// Mitsubishi GX Works2 project: Leser01-MF   PLC: Q03UDE
// Leser01-MF

PROGRAM MAIN
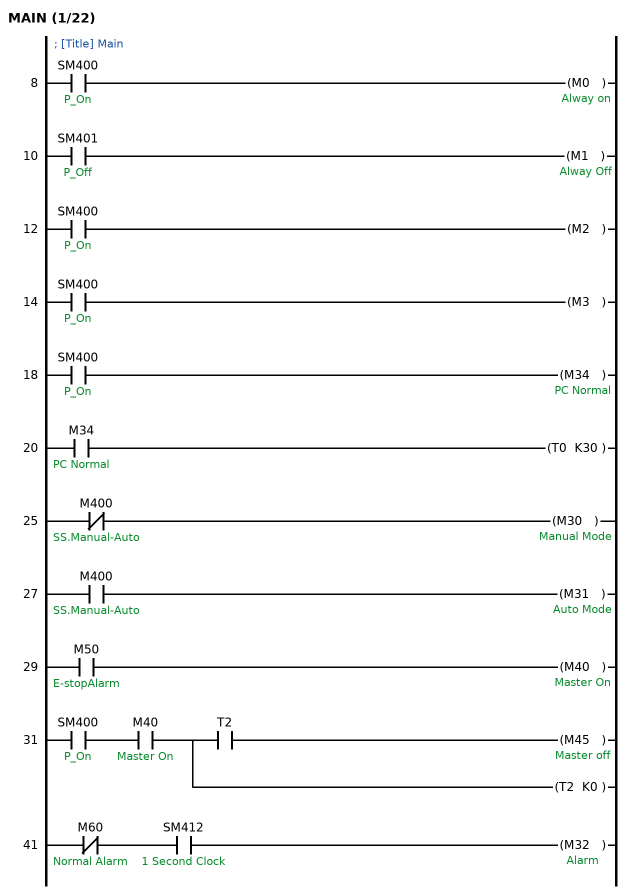
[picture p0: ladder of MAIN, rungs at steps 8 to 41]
; [Title] Main
8     LD      SM400  ; P_On
      OUT     M0  ; Alway on
10    LD      SM401  ; P_Off
      OUT     M1  ; Alway Off
12    LD      SM400  ; P_On
      OUT     M2
14    LD      SM400  ; P_On
      OUT     M3
; 
18    LD      SM400  ; P_On
      OUT     M34  ; PC Normal
20    LD      M34  ; PC Normal
      OUT     T0 K30
25    LDI     M400  ; SS.Manual-Auto
      OUT     M30  ; Manual Mode
27    LD      M400  ; SS.Manual-Auto
      OUT     M31  ; Auto Mode
29    LD      M50  ; E-stopAlarm
      OUT     M40  ; Master On
31    LD      SM400  ; P_On
      AND     M40  ; Master On
      MPS
      AND     T2
      OUT     M45  ; Master off
      MPP
      OUT     T2 K0
41    LDI     M60  ; Normal Alarm
      AND     SM412  ; 1 Second Clock
      OUT     M32  ; Alarm
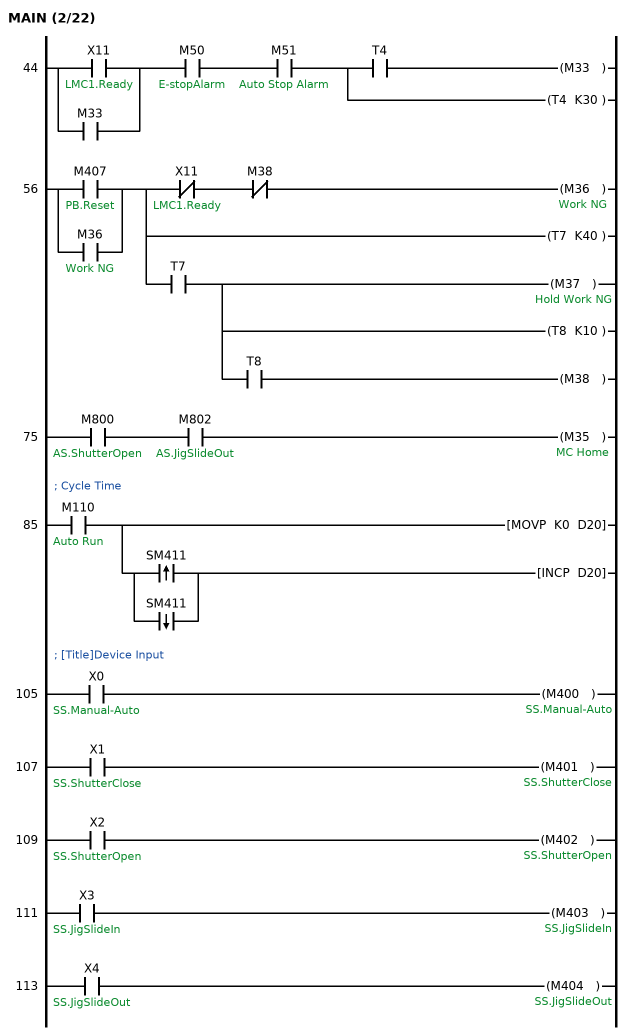
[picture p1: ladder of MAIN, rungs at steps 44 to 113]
44    LD      X11  ; LMC1.Ready
      OR      M33
      AND     M50  ; E-stopAlarm
      AND     M51  ; Auto Stop Alarm
      MPS
      AND     T4
      OUT     M33
      MPP
      OUT     T4 K30
56    LD      M407  ; PB.Reset
      OR      M36  ; Work NG
      MPS
      ANI     X11  ; LMC1.Ready
      ANI     M38
      OUT     M36  ; Work NG
      MPP
      OUT     T7 K40
      AND     T7
      OUT     M37  ; Hold Work NG
      OUT     T8 K10
      AND     T8
      OUT     M38
75    LD      M800  ; AS.ShutterOpen
      AND     M802  ; AS.JigSlideOut
      OUT     M35  ; MC Home
; Cycle Time
85    LD      M110  ; Auto Run
      MOVP    K0 D20
      LDP     SM411
      ORF     SM411
      ANB
      INCP    D20
; [Title]Device Input
105   LD      X0  ; SS.Manual-Auto
      OUT     M400  ; SS.Manual-Auto
107   LD      X1  ; SS.ShutterClose
      OUT     M401  ; SS.ShutterClose
109   LD      X2  ; SS.ShutterOpen
      OUT     M402  ; SS.ShutterOpen
111   LD      X3  ; SS.JigSlideIn
      OUT     M403  ; SS.JigSlideIn
113   LD      X4  ; SS.JigSlideOut
      OUT     M404  ; SS.JigSlideOut
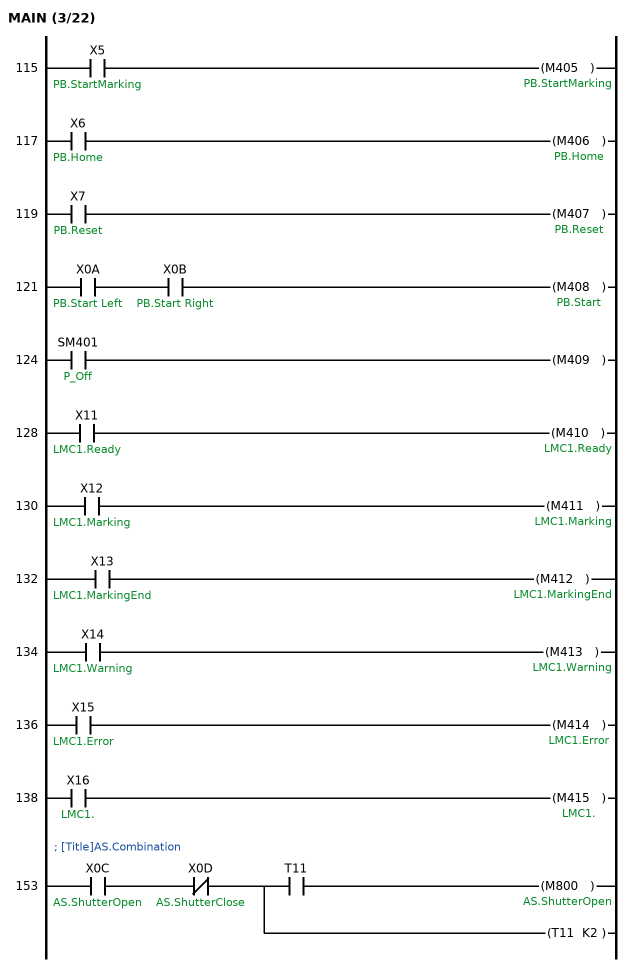
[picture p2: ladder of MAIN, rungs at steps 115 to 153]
115   LD      X5  ; PB.StartMarking
      OUT     M405  ; PB.StartMarking
117   LD      X6  ; PB.Home
      OUT     M406  ; PB.Home
119   LD      X7  ; PB.Reset
      OUT     M407  ; PB.Reset
121   LD      X0A  ; PB.Start Left
      AND     X0B  ; PB.Start Right
      OUT     M408  ; PB.Start
124   LD      SM401  ; P_Off
      OUT     M409
; 
128   LD      X11  ; LMC1.Ready
      OUT     M410  ; LMC1.Ready
130   LD      X12  ; LMC1.Marking
      OUT     M411  ; LMC1.Marking
132   LD      X13  ; LMC1.MarkingEnd
      OUT     M412  ; LMC1.MarkingEnd
134   LD      X14  ; LMC1.Warning
      OUT     M413  ; LMC1.Warning
136   LD      X15  ; LMC1.Error
      OUT     M414  ; LMC1.Error
138   LD      X16  ; LMC1.
      OUT     M415  ; LMC1.
; [Title]AS.Combination
153   LD      X0C  ; AS.ShutterOpen
      ANI     X0D  ; AS.ShutterClose
      MPS
      AND     T11
      OUT     M800  ; AS.ShutterOpen
      MPP
      OUT     T11 K2
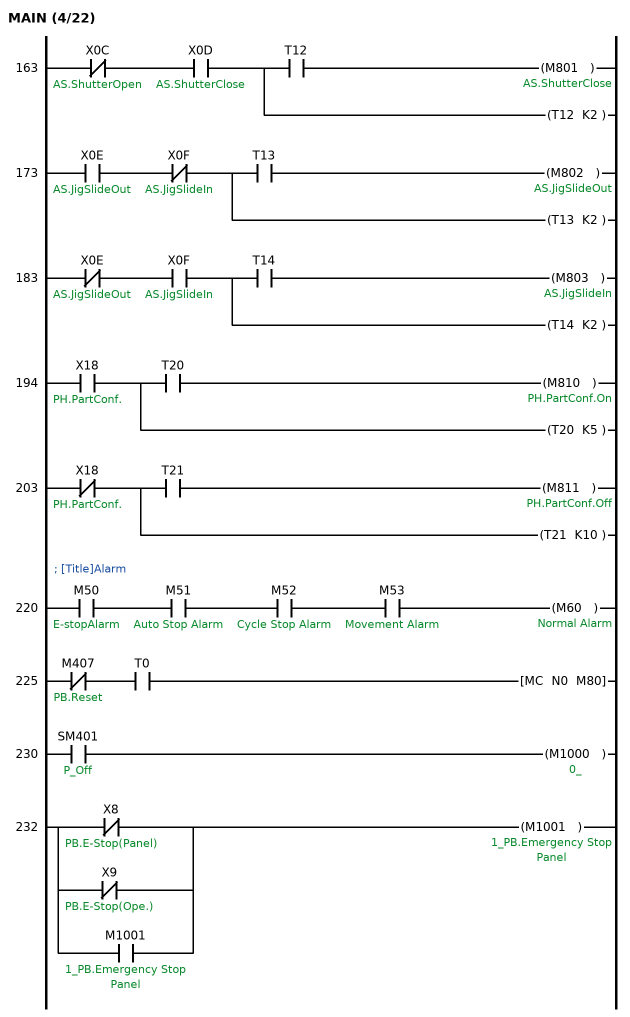
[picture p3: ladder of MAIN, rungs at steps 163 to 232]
163   LDI     X0C  ; AS.ShutterOpen
      AND     X0D  ; AS.ShutterClose
      MPS
      AND     T12
      OUT     M801  ; AS.ShutterClose
      MPP
      OUT     T12 K2
173   LD      X0E  ; AS.JigSlideOut
      ANI     X0F  ; AS.JigSlideIn
      MPS
      AND     T13
      OUT     M802  ; AS.JigSlideOut
      MPP
      OUT     T13 K2
183   LDI     X0E  ; AS.JigSlideOut
      AND     X0F  ; AS.JigSlideIn
      MPS
      AND     T14
      OUT     M803  ; AS.JigSlideIn
      MPP
      OUT     T14 K2
; 
194   LD      X18  ; PH.PartConf.
      MPS
      AND     T20
      OUT     M810  ; PH.PartConf.On
      MPP
      OUT     T20 K5
203   LDI     X18  ; PH.PartConf.
      MPS
      AND     T21
      OUT     M811  ; PH.PartConf.Off
      MPP
      OUT     T21 K10
; [Title]Alarm
220   LD      M50  ; E-stopAlarm
      AND     M51  ; Auto Stop Alarm
      AND     M52  ; Cycle Stop Alarm
      AND     M53  ; Movement Alarm
      OUT     M60  ; Normal Alarm
225   LDI     M407  ; PB.Reset
      AND     T0
      MC      N0 M80
; 
230   LD      SM401  ; P_Off
      OUT     M1000  ; 0_
232   LDI     X8  ; PB.E-Stop(Panel)
      ORI     X9  ; PB.E-Stop(Ope.)
      OR      M1001  ; 1_PB.Emergency Stop Panel
      OUT     M1001  ; 1_PB.Emergency Stop Panel
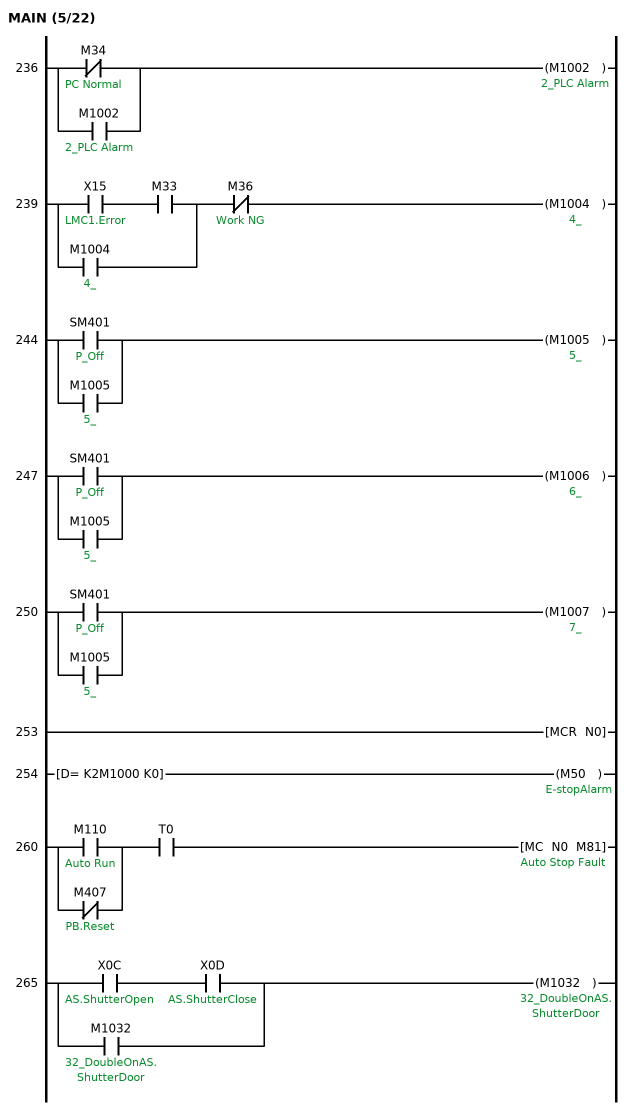
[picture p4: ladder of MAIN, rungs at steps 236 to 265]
236   LDI     M34  ; PC Normal
      OR      M1002  ; 2_PLC Alarm
      OUT     M1002  ; 2_PLC Alarm
239   LD      X15  ; LMC1.Error
      AND     M33
      OR      M1004  ; 4_
      ANI     M36  ; Work NG
      OUT     M1004  ; 4_
244   LD      SM401  ; P_Off
      OR      M1005  ; 5_
      OUT     M1005  ; 5_
247   LD      SM401  ; P_Off
      OR      M1005  ; 5_
      OUT     M1006  ; 6_
250   LD      SM401  ; P_Off
      OR      M1005  ; 5_
      OUT     M1007  ; 7_
253   MCR     N0
254   LDD=    K2M1000 K0  ; 0_
      OUT     M50  ; E-stopAlarm
; 
260   LD      M110  ; Auto Run
      ORI     M407  ; PB.Reset
      AND     T0
      MC      N0 M81  ; Auto Stop Fault
265   LD      X0C  ; AS.ShutterOpen
      AND     X0D  ; AS.ShutterClose
      OR      M1032  ; 32_DoubleOnAS.ShutterDoor
      OUT     M1032  ; 32_DoubleOnAS.ShutterDoor
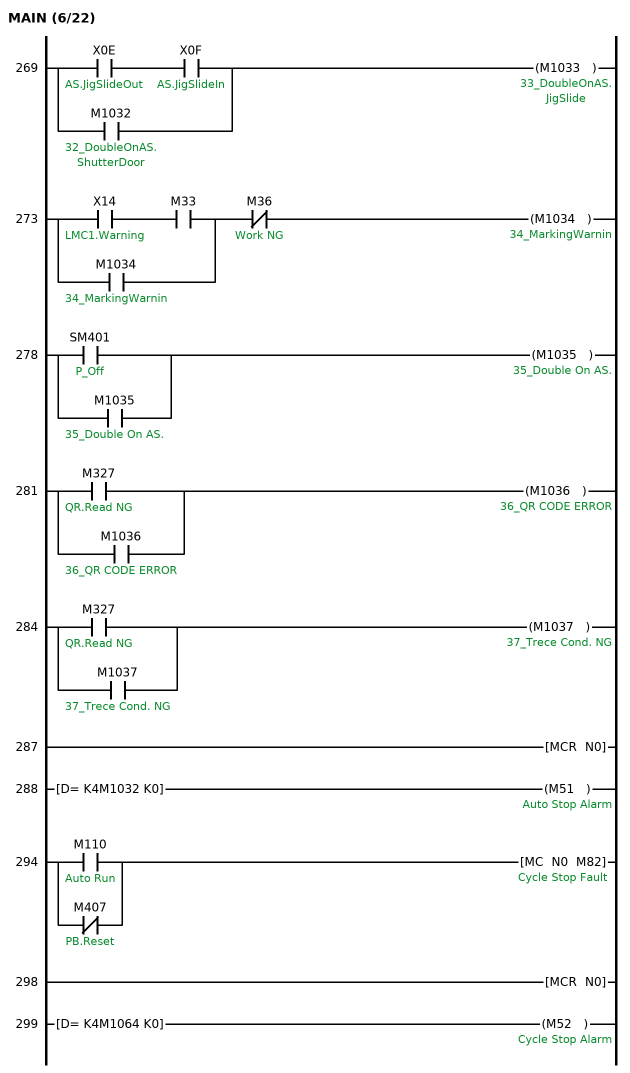
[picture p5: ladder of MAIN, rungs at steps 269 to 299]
269   LD      X0E  ; AS.JigSlideOut
      AND     X0F  ; AS.JigSlideIn
      OR      M1032  ; 32_DoubleOnAS.ShutterDoor
      OUT     M1033  ; 33_DoubleOnAS.JigSlide
273   LD      X14  ; LMC1.Warning
      AND     M33
      OR      M1034  ; 34_MarkingWarnin
      ANI     M36  ; Work NG
      OUT     M1034  ; 34_MarkingWarnin
278   LD      SM401  ; P_Off
      OR      M1035  ; 35_Double On AS.
      OUT     M1035  ; 35_Double On AS.
281   LD      M327  ; QR.Read NG
      OR      M1036  ; 36_QR CODE ERROR
      OUT     M1036  ; 36_QR CODE ERROR
284   LD      M327  ; QR.Read NG
      OR      M1037  ; 37_Trece Cond. NG
      OUT     M1037  ; 37_Trece Cond. NG
287   MCR     N0
288   LDD=    K4M1032 K0  ; 32_DoubleOnAS.ShutterDoor
      OUT     M51  ; Auto Stop Alarm
; 
294   LD      M110  ; Auto Run
      ORI     M407  ; PB.Reset
      MC      N0 M82  ; Cycle Stop Fault
298   MCR     N0
299   LDD=    K4M1064 K0  ; 64
      OUT     M52  ; Cycle Stop Alarm
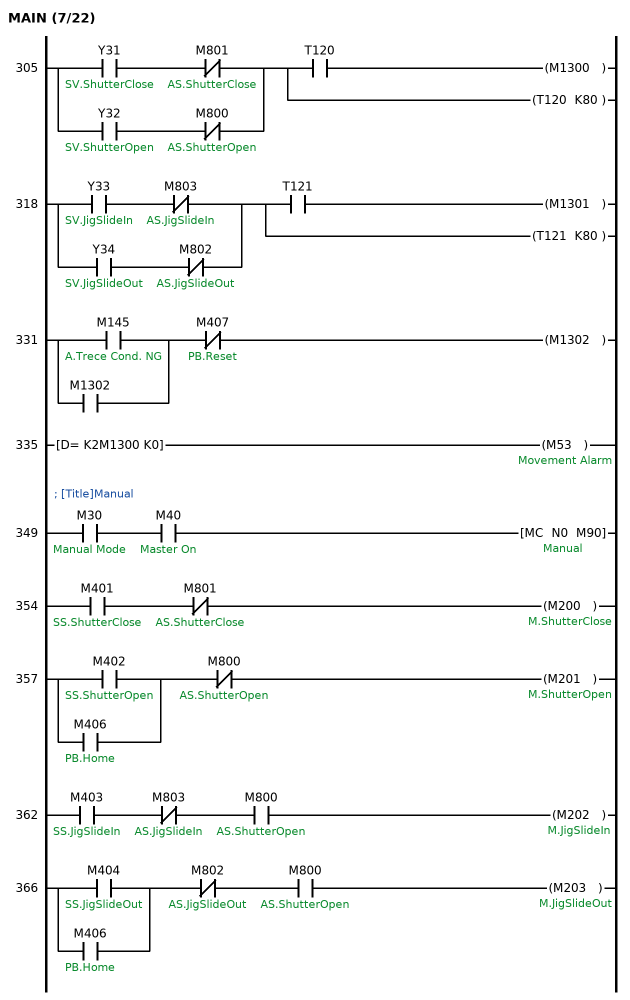
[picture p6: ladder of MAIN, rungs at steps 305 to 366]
; 
305   LD      Y31  ; SV.ShutterClose
      ANI     M801  ; AS.ShutterClose
      LD      Y32  ; SV.ShutterOpen
      ANI     M800  ; AS.ShutterOpen
      ORB
      MPS
      AND     T120
      OUT     M1300
      MPP
      OUT     T120 K80
318   LD      Y33  ; SV.JigSlideIn
      ANI     M803  ; AS.JigSlideIn
      LD      Y34  ; SV.JigSlideOut
      ANI     M802  ; AS.JigSlideOut
      ORB
      MPS
      AND     T121
      OUT     M1301
      MPP
      OUT     T121 K80
331   LD      M145  ; A.Trece Cond. NG
      OR      M1302
      ANI     M407  ; PB.Reset
      OUT     M1302
335   LDD=    K2M1300 K0
      OUT     M53  ; Movement Alarm
; [Title]Manual
349   LD      M30  ; Manual Mode
      AND     M40  ; Master On
      MC      N0 M90  ; Manual
; 
354   LD      M401  ; SS.ShutterClose
      ANI     M801  ; AS.ShutterClose
      OUT     M200  ; M.ShutterClose
357   LD      M402  ; SS.ShutterOpen
      OR      M406  ; PB.Home
      ANI     M800  ; AS.ShutterOpen
      OUT     M201  ; M.ShutterOpen
; 
362   LD      M403  ; SS.JigSlideIn
      ANI     M803  ; AS.JigSlideIn
      AND     M800  ; AS.ShutterOpen
      OUT     M202  ; M.JigSlideIn
366   LD      M404  ; SS.JigSlideOut
      OR      M406  ; PB.Home
      ANI     M802  ; AS.JigSlideOut
      AND     M800  ; AS.ShutterOpen
      OUT     M203  ; M.JigSlideOut
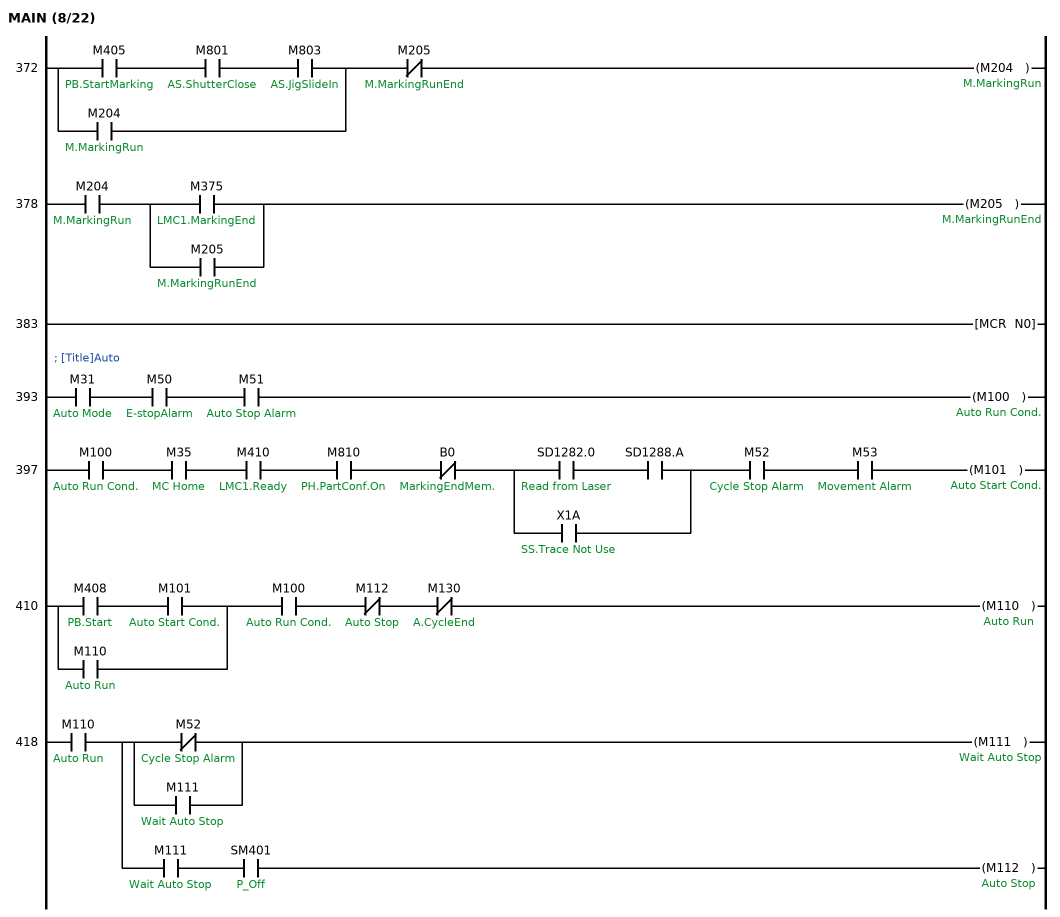
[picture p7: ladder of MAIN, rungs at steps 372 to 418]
; 
372   LD      M405  ; PB.StartMarking
      AND     M801  ; AS.ShutterClose
      AND     M803  ; AS.JigSlideIn
      OR      M204  ; M.MarkingRun
      ANI     M205  ; M.MarkingRunEnd
      OUT     M204  ; M.MarkingRun
378   LD      M204  ; M.MarkingRun
      LD      M375  ; LMC1.MarkingEnd
      OR      M205  ; M.MarkingRunEnd
      ANB
      OUT     M205  ; M.MarkingRunEnd
383   MCR     N0
; [Title]Auto
; 
393   LD      M31  ; Auto Mode
      AND     M50  ; E-stopAlarm
      AND     M51  ; Auto Stop Alarm
      OUT     M100  ; Auto Run Cond.
397   LD      M100  ; Auto Run Cond.
      AND     M35  ; MC Home
      AND     M410  ; LMC1.Ready
      AND     M810  ; PH.PartConf.On
      ANI     B0  ; MarkingEndMem.
      LD      SD1282.0  ; Read from Laser
      AND     SD1288.A
      OR      X1A  ; SS.Trace Not Use
      ANB
      AND     M52  ; Cycle Stop Alarm
      AND     M53  ; Movement Alarm
      OUT     M101  ; Auto Start Cond.
; 
410   LD      M408  ; PB.Start
      AND     M101  ; Auto Start Cond.
      OR      M110  ; Auto Run
      AND     M100  ; Auto Run Cond.
      ANI     M112  ; Auto Stop
      ANI     M130  ; A.CycleEnd
      OUT     M110  ; Auto Run
; 
418   LD      M110  ; Auto Run
      MPS
      LDI     M52  ; Cycle Stop Alarm
      OR      M111  ; Wait Auto Stop
      ANB
      OUT     M111  ; Wait Auto Stop
      MPP
      AND     M111  ; Wait Auto Stop
      AND     SM401  ; P_Off
      OUT     M112  ; Auto Stop
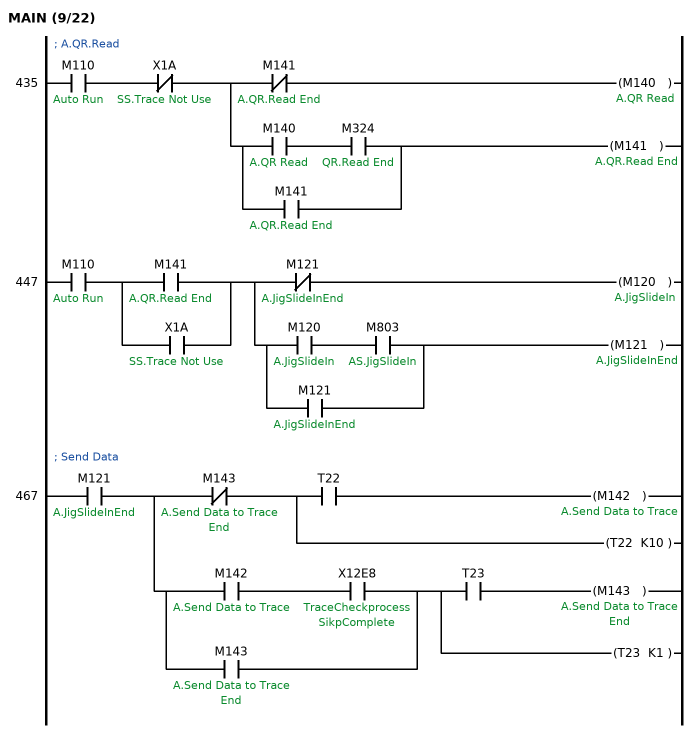
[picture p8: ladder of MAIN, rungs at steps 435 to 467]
; A.QR.Read
435   LD      M110  ; Auto Run
      ANI     X1A  ; SS.Trace Not Use
      MPS
      ANI     M141  ; A.QR.Read End
      OUT     M140  ; A.QR Read
      MPP
      LD      M140  ; A.QR Read
      AND     M324  ; QR.Read End
      OR      M141  ; A.QR.Read End
      ANB
      OUT     M141  ; A.QR.Read End
; 
447   LD      M110  ; Auto Run
      LD      M141  ; A.QR.Read End
      OR      X1A  ; SS.Trace Not Use
      ANB
      MPS
      ANI     M121  ; A.JigSlideInEnd
      OUT     M120  ; A.JigSlideIn
      MPP
      LD      M120  ; A.JigSlideIn
      AND     M803  ; AS.JigSlideIn
      OR      M121  ; A.JigSlideInEnd
      ANB
      OUT     M121  ; A.JigSlideInEnd
; Send Data
467   LD      M121  ; A.JigSlideInEnd
      MPS
      ANI     M143  ; A.Send Data to Trace End
      MPS
      AND     T22
      OUT     M142  ; A.Send Data to Trace
      MPP
      OUT     T22 K10
      MPP
      LD      M142  ; A.Send Data to Trace
      AND     X12E8  ; TraceCheckprocessSikpComplete
      OR      M143  ; A.Send Data to Trace End
      ANB
      MPS
      AND     T23
      OUT     M143  ; A.Send Data to Trace End
      MPP
      OUT     T23 K1
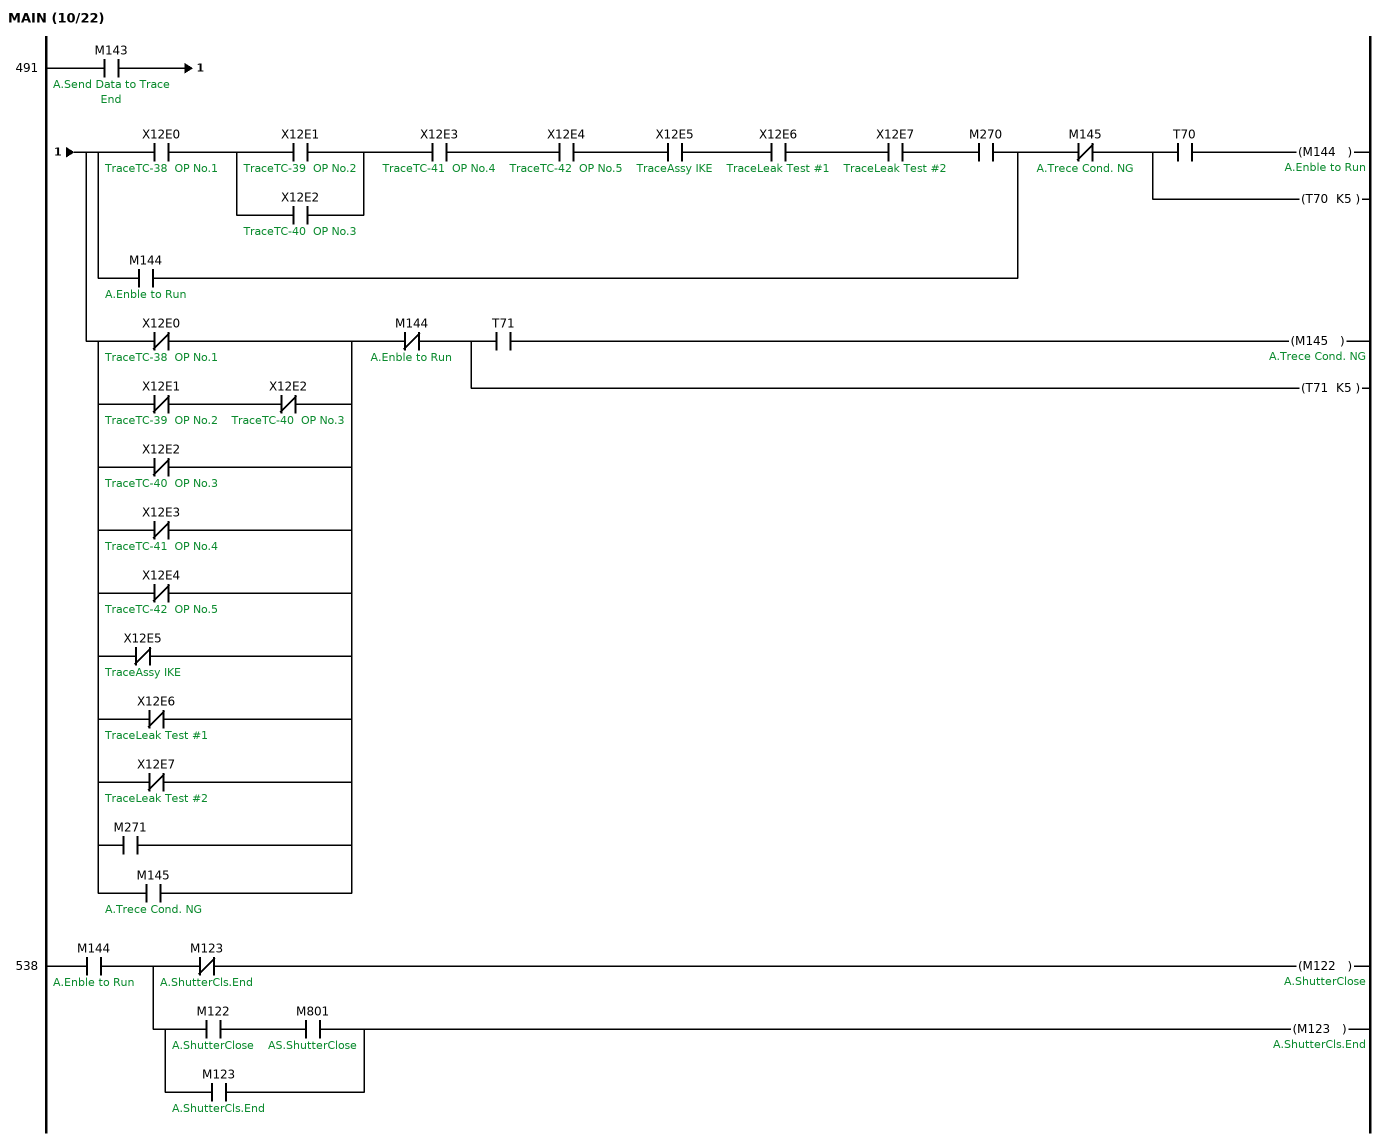
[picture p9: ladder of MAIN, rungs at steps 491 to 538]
491   LD      M143  ; A.Send Data to Trace End
      MPS
      LD      X12E0  ; TraceTC-38  OP No.1
      LD      X12E1  ; TraceTC-39  OP No.2
      OR      X12E2  ; TraceTC-40  OP No.3
      ANB
      AND     X12E3  ; TraceTC-41  OP No.4
      AND     X12E4  ; TraceTC-42  OP No.5
      AND     X12E5  ; TraceAssy IKE
      AND     X12E6  ; TraceLeak Test #1
      AND     X12E7  ; TraceLeak Test #2
      AND     M270
      OR      M144  ; A.Enble to Run
      ANB
      ANI     M145  ; A.Trece Cond. NG
      MPS
      AND     T70
      OUT     M144  ; A.Enble to Run
      MPP
      OUT     T70 K5
      MPP
      LDI     X12E0  ; TraceTC-38  OP No.1
      LDI     X12E1  ; TraceTC-39  OP No.2
      ANI     X12E2  ; TraceTC-40  OP No.3
      ORB
      ORI     X12E2  ; TraceTC-40  OP No.3
      ORI     X12E3  ; TraceTC-41  OP No.4
      ORI     X12E4  ; TraceTC-42  OP No.5
      ORI     X12E5  ; TraceAssy IKE
      ORI     X12E6  ; TraceLeak Test #1
      ORI     X12E7  ; TraceLeak Test #2
      OR      M271
      OR      M145  ; A.Trece Cond. NG
      ANB
      ANI     M144  ; A.Enble to Run
      MPS
      AND     T71
      OUT     M145  ; A.Trece Cond. NG
      MPP
      OUT     T71 K5
; 
538   LD      M144  ; A.Enble to Run
      MPS
      ANI     M123  ; A.ShutterCls.End
      OUT     M122  ; A.ShutterClose
      MPP
      LD      M122  ; A.ShutterClose
      AND     M801  ; AS.ShutterClose
      OR      M123  ; A.ShutterCls.End
      ANB
      OUT     M123  ; A.ShutterCls.End
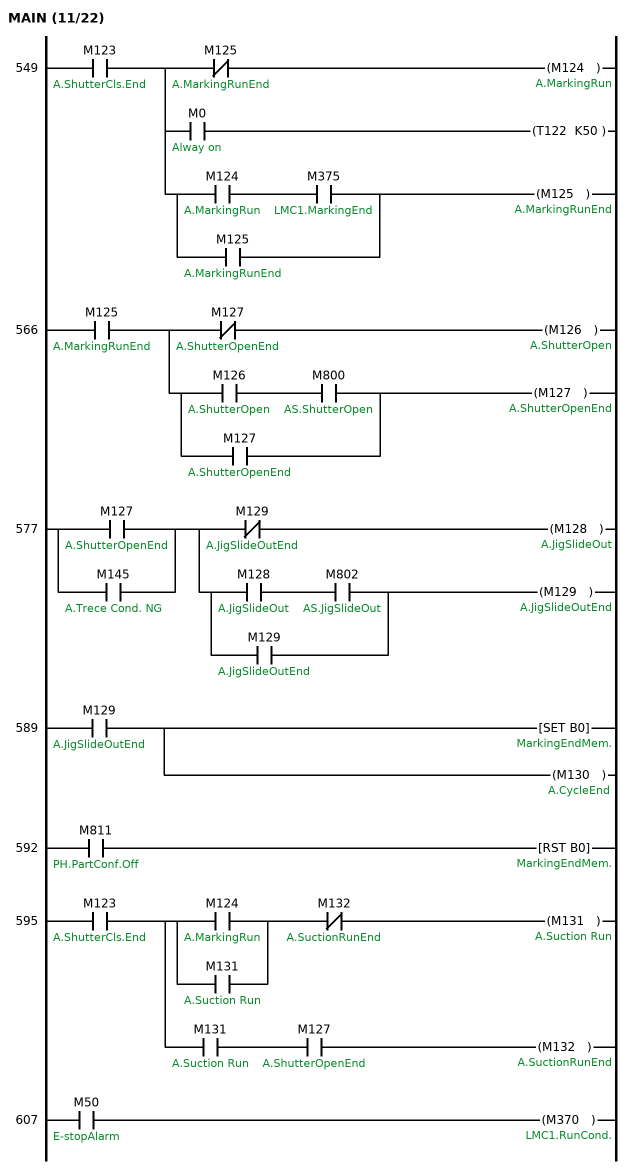
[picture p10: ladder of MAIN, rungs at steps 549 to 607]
; 
549   LD      M123  ; A.ShutterCls.End
      MPS
      ANI     M125  ; A.MarkingRunEnd
      OUT     M124  ; A.MarkingRun
      MRD
      AND     M0  ; Alway on
      OUT     T122 K50
      MPP
      LD      M124  ; A.MarkingRun
      AND     M375  ; LMC1.MarkingEnd
      OR      M125  ; A.MarkingRunEnd
      ANB
      OUT     M125  ; A.MarkingRunEnd
; 
566   LD      M125  ; A.MarkingRunEnd
      MPS
      ANI     M127  ; A.ShutterOpenEnd
      OUT     M126  ; A.ShutterOpen
      MPP
      LD      M126  ; A.ShutterOpen
      AND     M800  ; AS.ShutterOpen
      OR      M127  ; A.ShutterOpenEnd
      ANB
      OUT     M127  ; A.ShutterOpenEnd
; 
577   LD      M127  ; A.ShutterOpenEnd
      OR      M145  ; A.Trece Cond. NG
      MPS
      ANI     M129  ; A.JigSlideOutEnd
      OUT     M128  ; A.JigSlideOut
      MPP
      LD      M128  ; A.JigSlideOut
      AND     M802  ; AS.JigSlideOut
      OR      M129  ; A.JigSlideOutEnd
      ANB
      OUT     M129  ; A.JigSlideOutEnd
; 
589   LD      M129  ; A.JigSlideOutEnd
      SET     B0  ; MarkingEndMem.
      OUT     M130  ; A.CycleEnd
592   LD      M811  ; PH.PartConf.Off
      RST     B0  ; MarkingEndMem.
; 
595   LD      M123  ; A.ShutterCls.End
      MPS
      LD      M124  ; A.MarkingRun
      OR      M131  ; A.Suction Run
      ANB
      ANI     M132  ; A.SuctionRunEnd
      OUT     M131  ; A.Suction Run
      MPP
      AND     M131  ; A.Suction Run
      AND     M127  ; A.ShutterOpenEnd
      OUT     M132  ; A.SuctionRunEnd
; 
607   LD      M50  ; E-stopAlarm
      OUT     M370  ; LMC1.RunCond.
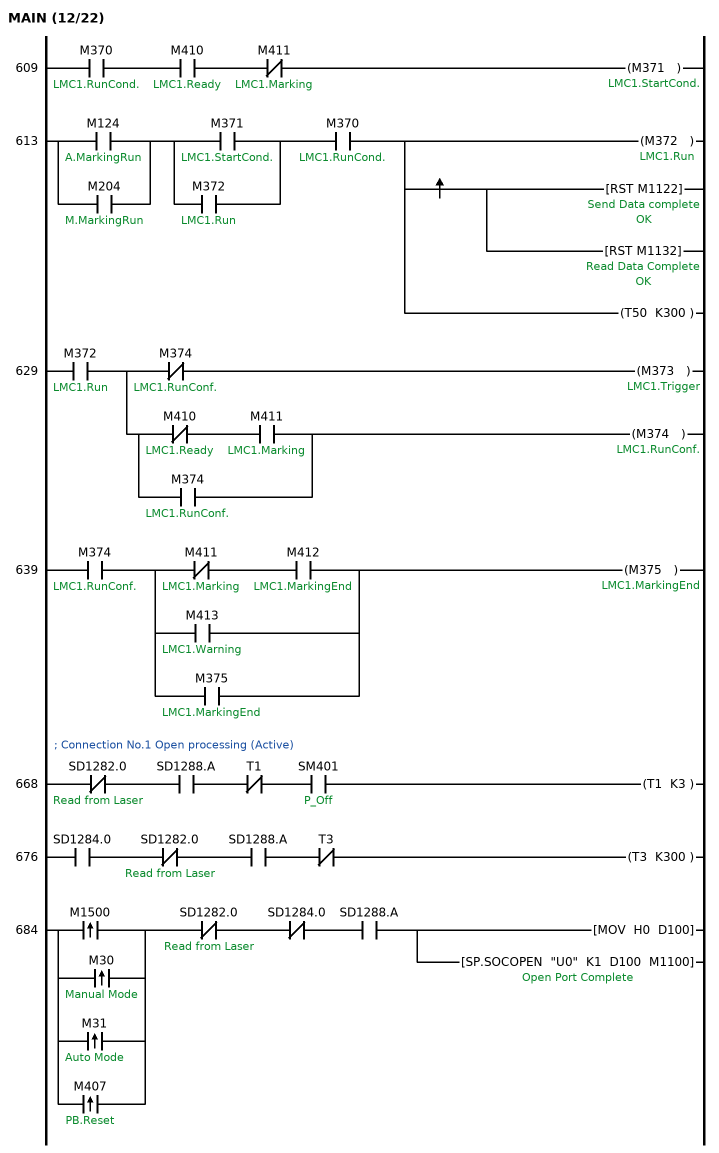
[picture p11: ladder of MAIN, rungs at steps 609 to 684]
609   LD      M370  ; LMC1.RunCond.
      AND     M410  ; LMC1.Ready
      ANI     M411  ; LMC1.Marking
      OUT     M371  ; LMC1.StartCond.
613   LD      M124  ; A.MarkingRun
      OR      M204  ; M.MarkingRun
      LD      M371  ; LMC1.StartCond.
      OR      M372  ; LMC1.Run
      ANB
      AND     M370  ; LMC1.RunCond.
      OUT     M372  ; LMC1.Run
      MPS
      MEP
      RST     M1122  ; Send Data complete OK
      RST     M1132  ; Read Data Complete OK
      MPP
      OUT     T50 K300
629   LD      M372  ; LMC1.Run
      MPS
      ANI     M374  ; LMC1.RunConf.
      OUT     M373  ; LMC1.Trigger
      MPP
      LDI     M410  ; LMC1.Ready
      AND     M411  ; LMC1.Marking
      OR      M374  ; LMC1.RunConf.
      ANB
      OUT     M374  ; LMC1.RunConf.
639   LD      M374  ; LMC1.RunConf.
      LDI     M411  ; LMC1.Marking
      AND     M412  ; LMC1.MarkingEnd
      OR      M413  ; LMC1.Warning
      OR      M375  ; LMC1.MarkingEnd
      ANB
      OUT     M375  ; LMC1.MarkingEnd
; Connection No.1 Open processing (Active)
668   LDI     SD1282.0  ; Read from Laser
      AND     SD1288.A
      ANI     T1
      AND     SM401  ; P_Off
      OUT     T1 K3
676   LD      SD1284.0
      ANI     SD1282.0  ; Read from Laser
      AND     SD1288.A
      ANI     T3
      OUT     T3 K300
684   LDP     M1500
      ORP     M30  ; Manual Mode
      ORP     M31  ; Auto Mode
      ORP     M407  ; PB.Reset
      ANI     SD1282.0  ; Read from Laser
      ANI     SD1284.0
      AND     SD1288.A
      MOV     H0 D100
      SP.SOCOPEN "U0" K1 D100 M1100  ; Open Port Complete
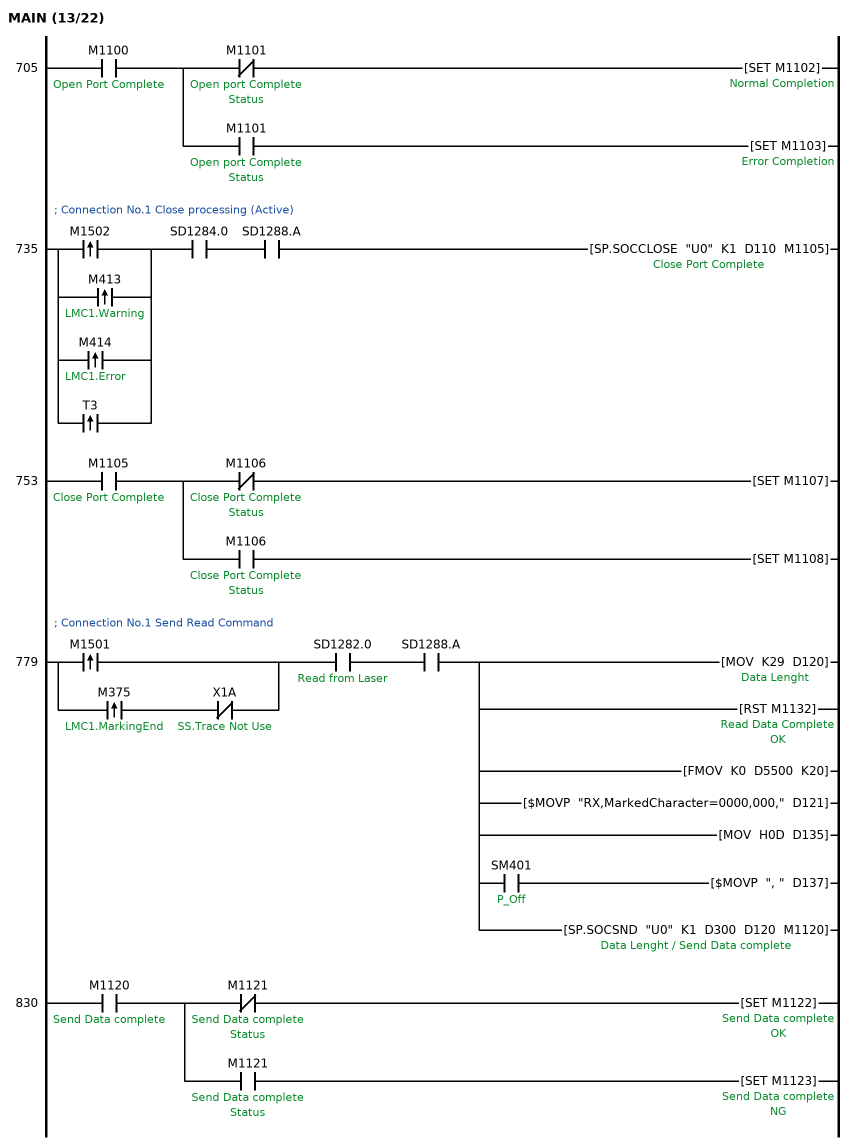
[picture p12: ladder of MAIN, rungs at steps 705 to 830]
705   LD      M1100  ; Open Port Complete
      MPS
      ANI     M1101  ; Open port Complete Status
      SET     M1102  ; Normal Completion
      MPP
      AND     M1101  ; Open port Complete Status
      SET     M1103  ; Error Completion
; Connection No.1 Close processing (Active)
735   LDP     M1502
      ORP     M413  ; LMC1.Warning
      ORP     M414  ; LMC1.Error
      ORP     T3
      AND     SD1284.0
      AND     SD1288.A
      SP.SOCCLOSE "U0" K1 D110 M1105  ; Close Port Complete
753   LD      M1105  ; Close Port Complete
      MPS
      ANI     M1106  ; Close Port Complete Status
      SET     M1107
      MPP
      AND     M1106  ; Close Port Complete Status
      SET     M1108
; Connection No.1 Send Read Command
779   LDP     M1501
      LDP     M375  ; LMC1.MarkingEnd
      ANI     X1A  ; SS.Trace Not Use
      ORB
      AND     SD1282.0  ; Read from Laser
      AND     SD1288.A
      MOV     K29 D120  ; Data Lenght
      RST     M1132  ; Read Data Complete OK
      FMOV    K0 D5500 K20
      $MOVP   "RX,MarkedCharacter=0000,000," D121
      MOV     H0D D135
      MPS
      AND     SM401  ; P_Off
      $MOVP   ", " D137
      MPP
      SP.SOCSND "U0" K1 D300 D120 M1120  ; Send Data complete
830   LD      M1120  ; Send Data complete
      MPS
      ANI     M1121  ; Send Data complete Status
      SET     M1122  ; Send Data complete OK
      MPP
      AND     M1121  ; Send Data complete Status
      SET     M1123  ; Send Data complete NG
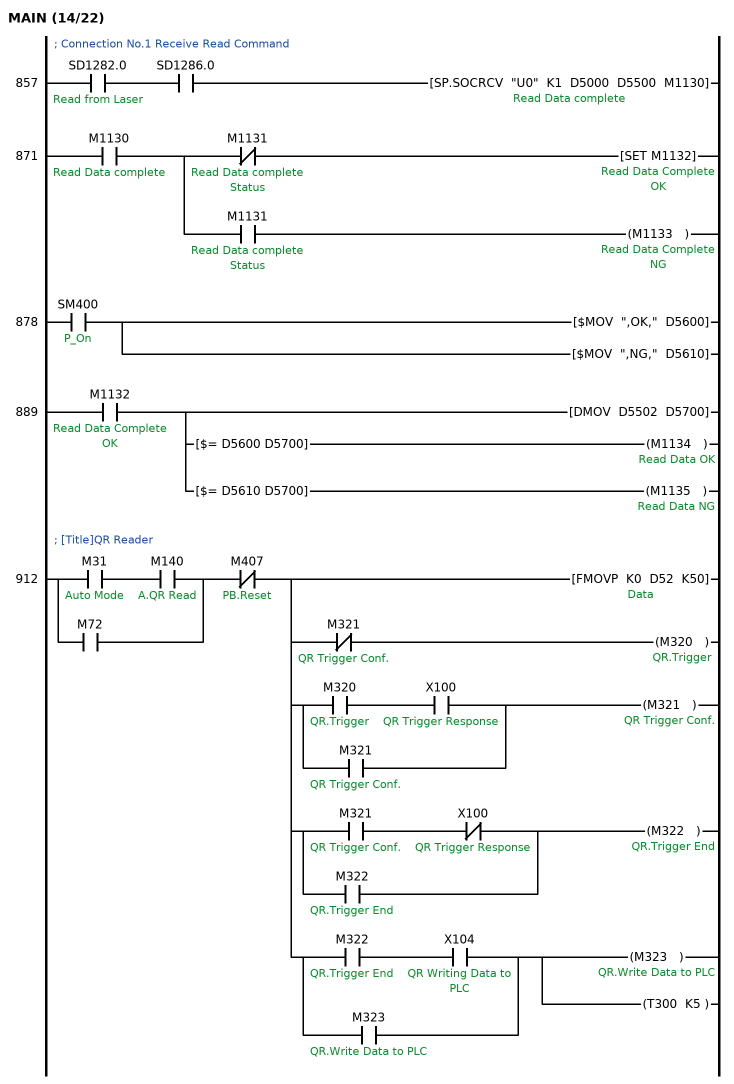
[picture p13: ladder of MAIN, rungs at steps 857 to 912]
; Connection No.1 Receive Read Command
857   LD      SD1282.0  ; Read from Laser
      AND     SD1286.0
      SP.SOCRCV "U0" K1 D5000 D5500 M1130  ; Read Data complete
871   LD      M1130  ; Read Data complete
      MPS
      ANI     M1131  ; Read Data complete Status
      SET     M1132  ; Read Data Complete OK
      MPP
      AND     M1131  ; Read Data complete Status
      OUT     M1133  ; Read Data Complete NG
878   LD      SM400  ; P_On
      $MOV    ",OK," D5600
      $MOV    ",NG," D5610
889   LD      M1132  ; Read Data Complete OK
      DMOV    D5502 D5700
      MPS
      AND$=   D5600 D5700
      OUT     M1134  ; Read Data OK
      MPP
      AND$=   D5610 D5700
      OUT     M1135  ; Read Data NG
; [Title]QR Reader
912   LD      M31  ; Auto Mode
      AND     M140  ; A.QR Read
      OR      M72
      ANI     M407  ; PB.Reset
      FMOVP   K0 D52 K50  ; Data
      MPS
      ANI     M321  ; QR Trigger Conf.
      OUT     M320  ; QR.Trigger
      MRD
      LD      M320  ; QR.Trigger
      AND     X100  ; QR Trigger Response
      OR      M321  ; QR Trigger Conf.
      ANB
      OUT     M321  ; QR Trigger Conf.
      MRD
      LD      M321  ; QR Trigger Conf.
      ANI     X100  ; QR Trigger Response
      OR      M322  ; QR.Trigger End
      ANB
      OUT     M322  ; QR.Trigger End
      MPP
      LD      M322  ; QR.Trigger End
      AND     X104  ; QR Writing Data to PLC
      OR      M323  ; QR.Write Data to PLC
      ANB
      OUT     M323  ; QR.Write Data to PLC
      OUT     T300 K5
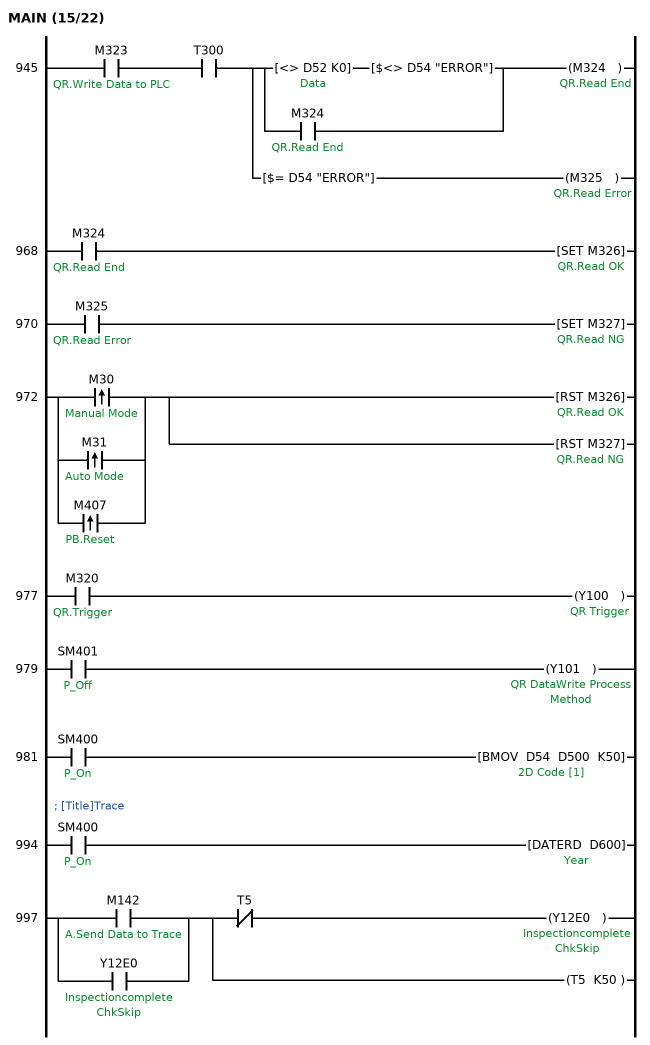
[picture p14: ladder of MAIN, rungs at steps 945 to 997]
945   LD      M323  ; QR.Write Data to PLC
      AND     T300
      MPS
      LD<>    D52 K0  ; Data
      AND$<>  D54 "ERROR"
      OR      M324  ; QR.Read End
      ANB
      OUT     M324  ; QR.Read End
      MPP
      AND$=   D54 "ERROR"
      OUT     M325  ; QR.Read Error
968   LD      M324  ; QR.Read End
      SET     M326  ; QR.Read OK
970   LD      M325  ; QR.Read Error
      SET     M327  ; QR.Read NG
972   LDP     M30  ; Manual Mode
      ORP     M31  ; Auto Mode
      ORP     M407  ; PB.Reset
      RST     M326  ; QR.Read OK
      RST     M327  ; QR.Read NG
977   LD      M320  ; QR.Trigger
      OUT     Y100  ; QR Trigger
979   LD      SM401  ; P_Off
      OUT     Y101  ; QR DataWrite Process Method
981   LD      SM400  ; P_On
      BMOV    D54 D500 K50  ; 2D Code [1]
; [Title]Trace
994   LD      SM400  ; P_On
      DATERD  D600  ; Year
997   LD      M142  ; A.Send Data to Trace
      OR      Y12E0  ; InspectioncompleteChkSkip
      MPS
      ANI     T5
      OUT     Y12E0  ; InspectioncompleteChkSkip
      MPP
      OUT     T5 K50
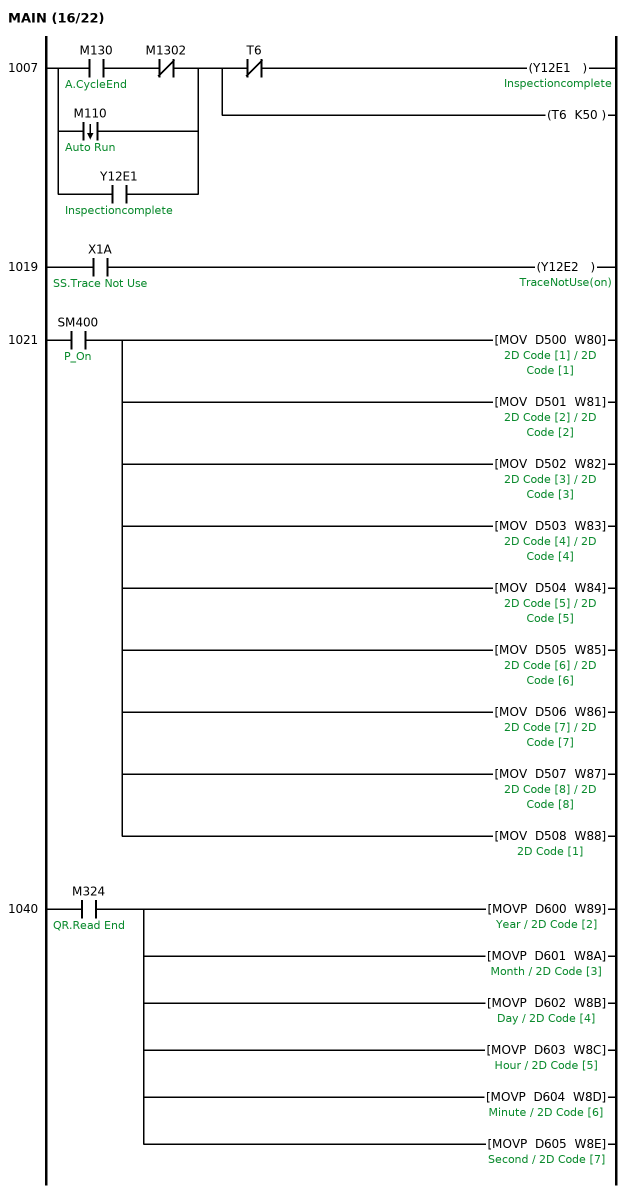
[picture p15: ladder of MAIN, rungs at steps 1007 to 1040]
1007  LD      M130  ; A.CycleEnd
      ANI     M1302
      ORF     M110  ; Auto Run
      OR      Y12E1  ; Inspectioncomplete
      MPS
      ANI     T6
      OUT     Y12E1  ; Inspectioncomplete
      MPP
      OUT     T6 K50
1019  LD      X1A  ; SS.Trace Not Use
      OUT     Y12E2  ; TraceNotUse(on)
1021  LD      SM400  ; P_On
      MOV     D500 W80  ; 2D Code [1]
      MOV     D501 W81  ; 2D Code [2] / 2D Code [2]
      MOV     D502 W82  ; 2D Code [3] / 2D Code [3]
      MOV     D503 W83  ; 2D Code [4] / 2D Code [4]
      MOV     D504 W84  ; 2D Code [5] / 2D Code [5]
      MOV     D505 W85  ; 2D Code [6] / 2D Code [6]
      MOV     D506 W86  ; 2D Code [7] / 2D Code [7]
      MOV     D507 W87  ; 2D Code [8] / 2D Code [8]
      MOV     D508 W88  ; 2D Code [1]
1040  LD      M324  ; QR.Read End
      MOVP    D600 W89  ; 2D Code [2]
      MOVP    D601 W8A  ; Month / 2D Code [3]
      MOVP    D602 W8B  ; Day / 2D Code [4]
      MOVP    D603 W8C  ; Hour / 2D Code [5]
      MOVP    D604 W8D  ; Minute / 2D Code [6]
      MOVP    D605 W8E  ; Second / 2D Code [7]
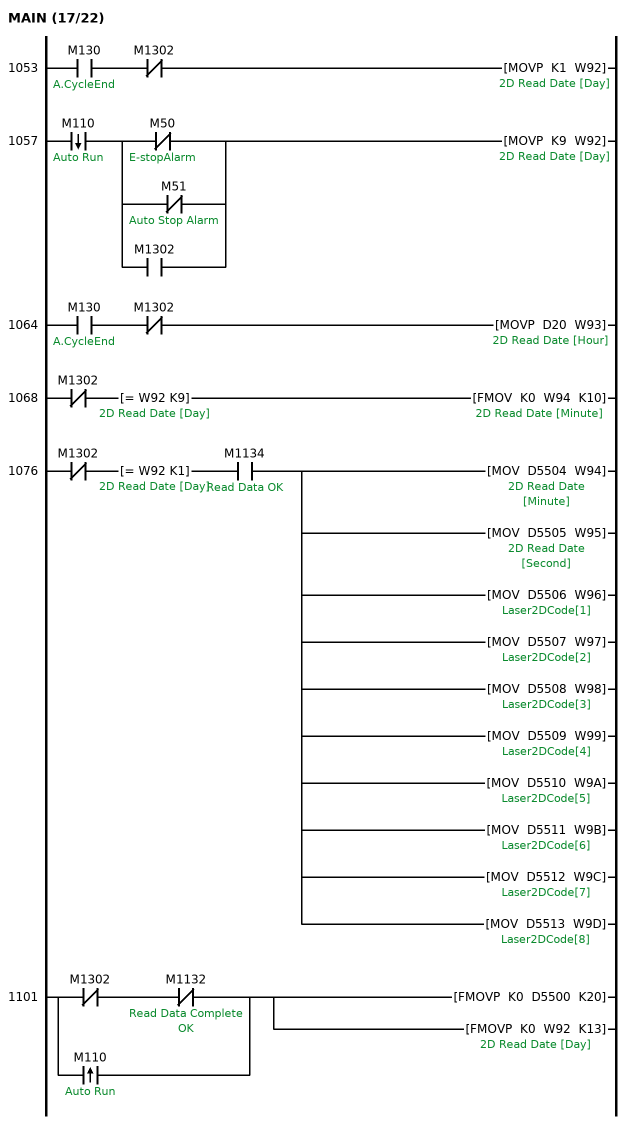
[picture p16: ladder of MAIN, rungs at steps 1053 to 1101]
1053  LD      M130  ; A.CycleEnd
      ANI     M1302
      MOVP    K1 W92  ; 2D Read Date [Day]
1057  LDF     M110  ; Auto Run
      LDI     M50  ; E-stopAlarm
      ORI     M51  ; Auto Stop Alarm
      OR      M1302
      ANB
      MOVP    K9 W92
1064  LD      M130  ; A.CycleEnd
      ANI     M1302
      MOVP    D20 W93  ; 2D Read Date [Hour]
1068  LDI     M1302
      AND=    W92 K9  ; 2D Read Date [Day]
      FMOV    K0 W94 K10  ; 2D Read Date [Minute]
1076  LDI     M1302
      AND=    W92 K1  ; 2D Read Date [Day]
      AND     M1134  ; Read Data OK
      MOV     D5504 W94
      MOV     D5505 W95  ; 2D Read Date [Second]
      MOV     D5506 W96  ; Laser2DCode[1]
      MOV     D5507 W97  ; Laser2DCode[2]
      MOV     D5508 W98  ; Laser2DCode[3]
      MOV     D5509 W99  ; Laser2DCode[4]
      MOV     D5510 W9A  ; Laser2DCode[5]
      MOV     D5511 W9B  ; Laser2DCode[6]
      MOV     D5512 W9C  ; Laser2DCode[7]
      MOV     D5513 W9D  ; Laser2DCode[8]
1101  LDI     M1302
      ANI     M1132  ; Read Data Complete OK
      ORP     M110  ; Auto Run
      FMOVP   K0 D5500 K20
      FMOVP   K0 W92 K13
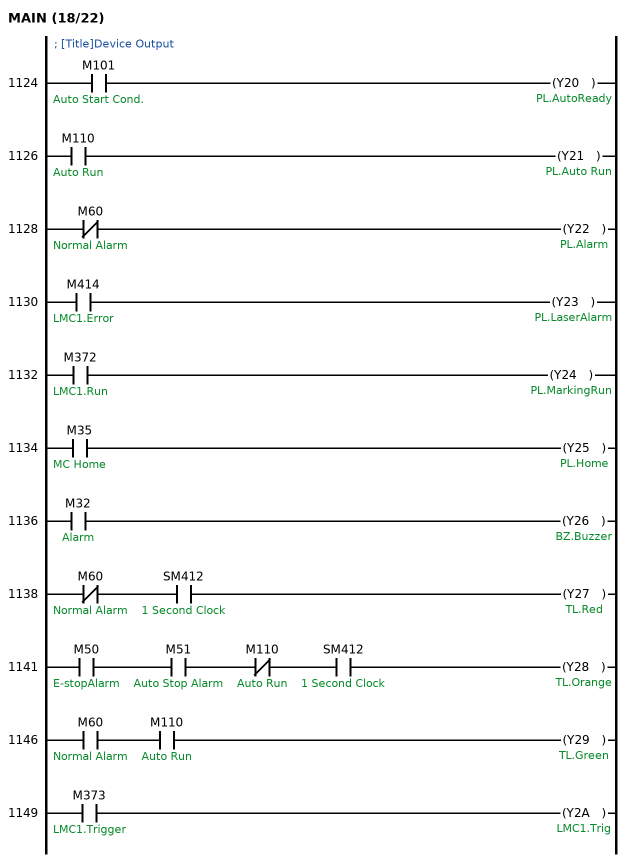
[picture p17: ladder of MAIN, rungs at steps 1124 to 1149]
; [Title]Device Output
1124  LD      M101  ; Auto Start Cond.
      OUT     Y20  ; PL.AutoReady
1126  LD      M110  ; Auto Run
      OUT     Y21  ; PL.Auto Run
1128  LDI     M60  ; Normal Alarm
      OUT     Y22  ; PL.Alarm
1130  LD      M414  ; LMC1.Error
      OUT     Y23  ; PL.LaserAlarm
1132  LD      M372  ; LMC1.Run
      OUT     Y24  ; PL.MarkingRun
1134  LD      M35  ; MC Home
      OUT     Y25  ; PL.Home
1136  LD      M32  ; Alarm
      OUT     Y26  ; BZ.Buzzer
1138  LDI     M60  ; Normal Alarm
      AND     SM412  ; 1 Second Clock
      OUT     Y27  ; TL.Red
1141  LD      M50  ; E-stopAlarm
      AND     M51  ; Auto Stop Alarm
      ANI     M110  ; Auto Run
      AND     SM412  ; 1 Second Clock
      OUT     Y28  ; TL.Orange
1146  LD      M60  ; Normal Alarm
      AND     M110  ; Auto Run
      OUT     Y29  ; TL.Green
1149  LD      M373  ; LMC1.Trigger
      OUT     Y2A  ; LMC1.Trig
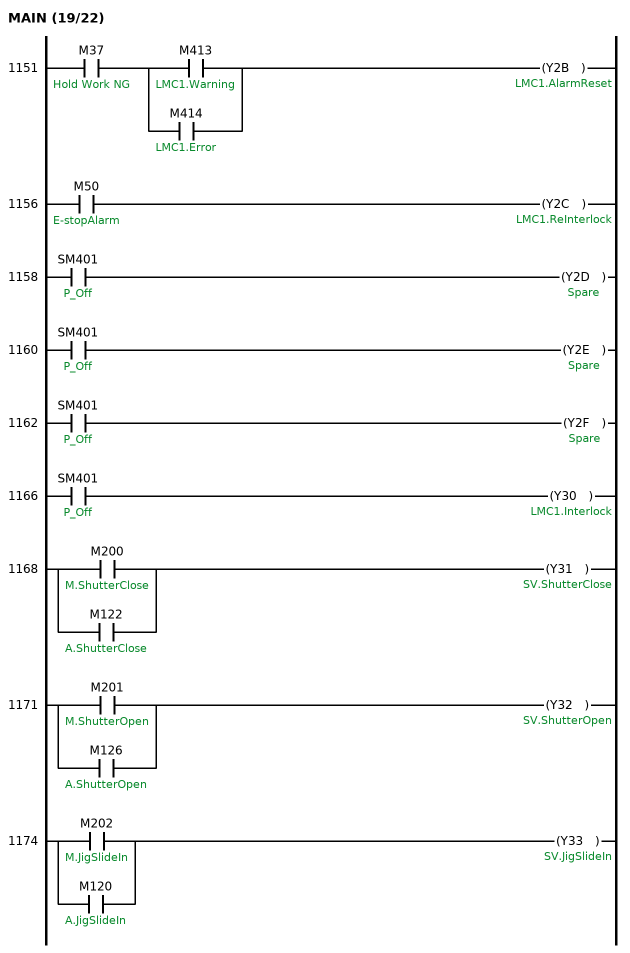
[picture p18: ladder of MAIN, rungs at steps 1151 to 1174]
1151  LD      M37  ; Hold Work NG
      LD      M413  ; LMC1.Warning
      OR      M414  ; LMC1.Error
      ANB
      OUT     Y2B  ; LMC1.AlarmReset
1156  LD      M50  ; E-stopAlarm
      OUT     Y2C  ; LMC1.ReInterlock
1158  LD      SM401  ; P_Off
      OUT     Y2D  ; Spare
1160  LD      SM401  ; P_Off
      OUT     Y2E  ; Spare
1162  LD      SM401  ; P_Off
      OUT     Y2F  ; Spare
; 
1166  LD      SM401  ; P_Off
      OUT     Y30  ; LMC1.Interlock
1168  LD      M200  ; M.ShutterClose
      OR      M122  ; A.ShutterClose
      OUT     Y31  ; SV.ShutterClose
1171  LD      M201  ; M.ShutterOpen
      OR      M126  ; A.ShutterOpen
      OUT     Y32  ; SV.ShutterOpen
1174  LD      M202  ; M.JigSlideIn
      OR      M120  ; A.JigSlideIn
      OUT     Y33  ; SV.JigSlideIn
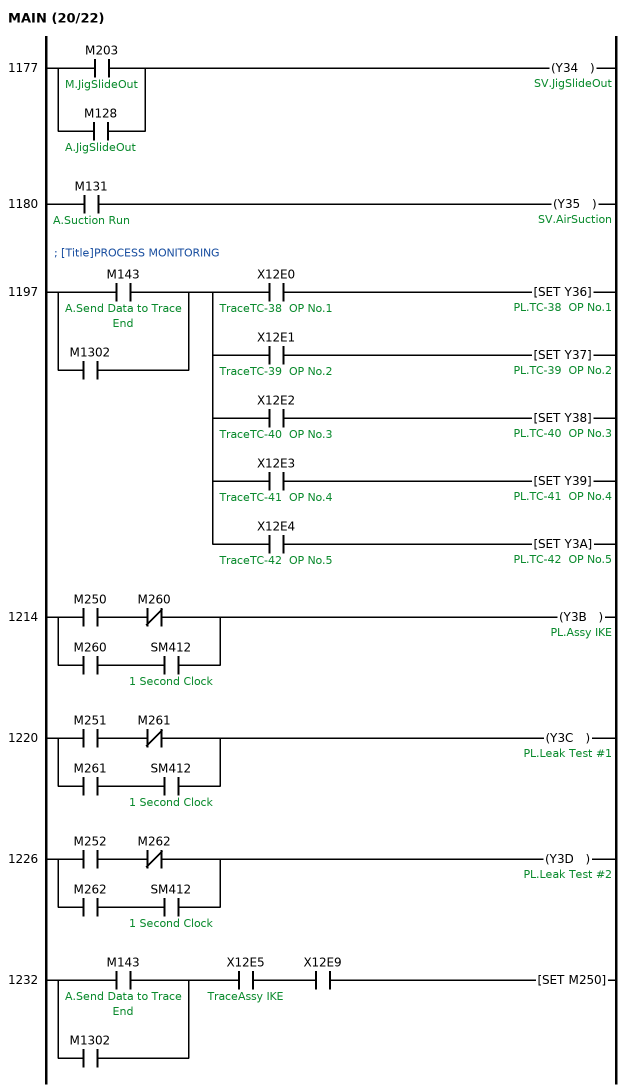
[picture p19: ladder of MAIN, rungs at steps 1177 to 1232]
1177  LD      M203  ; M.JigSlideOut
      OR      M128  ; A.JigSlideOut
      OUT     Y34  ; SV.JigSlideOut
1180  LD      M131  ; A.Suction Run
      OUT     Y35  ; SV.AirSuction
; [Title]PROCESS MONITORING
1197  LD      M143  ; A.Send Data to Trace End
      OR      M1302
      MPS
      AND     X12E0  ; TraceTC-38  OP No.1
      SET     Y36  ; PL.TC-38  OP No.1
      MRD
      AND     X12E1  ; TraceTC-39  OP No.2
      SET     Y37  ; PL.TC-39  OP No.2
      MRD
      AND     X12E2  ; TraceTC-40  OP No.3
      SET     Y38  ; PL.TC-40  OP No.3
      MRD
      AND     X12E3  ; TraceTC-41  OP No.4
      SET     Y39  ; PL.TC-41  OP No.4
      MPP
      AND     X12E4  ; TraceTC-42  OP No.5
      SET     Y3A  ; PL.TC-42  OP No.5
1214  LD      M250
      ANI     M260
      LD      M260
      AND     SM412  ; 1 Second Clock
      ORB
      OUT     Y3B  ; PL.Assy IKE
1220  LD      M251
      ANI     M261
      LD      M261
      AND     SM412  ; 1 Second Clock
      ORB
      OUT     Y3C  ; PL.Leak Test #1
1226  LD      M252
      ANI     M262
      LD      M262
      AND     SM412  ; 1 Second Clock
      ORB
      OUT     Y3D  ; PL.Leak Test #2
1232  LD      M143  ; A.Send Data to Trace End
      OR      M1302
      AND     X12E5  ; TraceAssy IKE
      AND     X12E9
      SET     M250
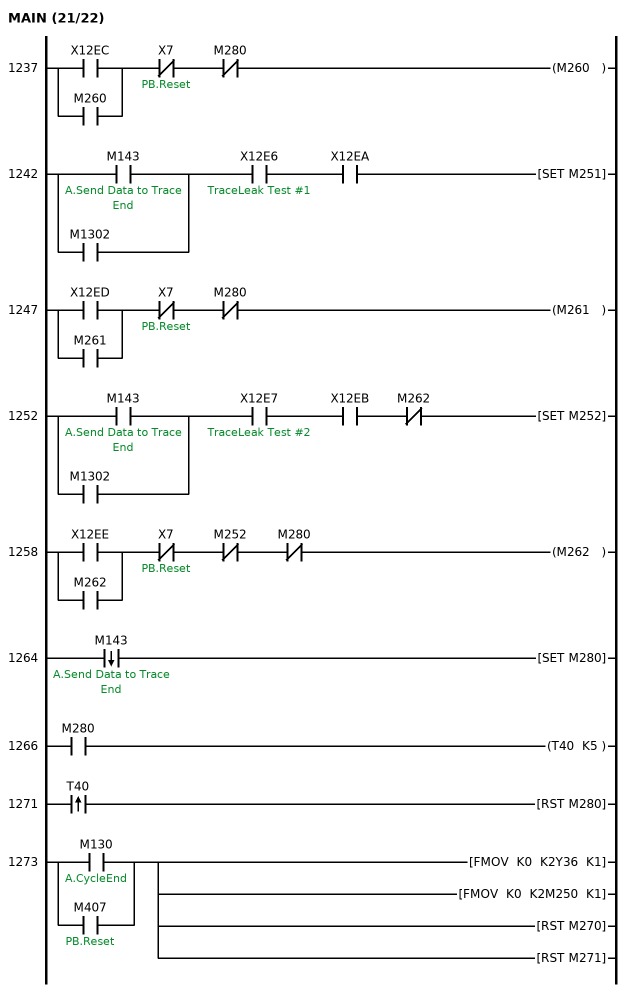
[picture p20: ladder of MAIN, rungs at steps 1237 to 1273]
1237  LD      X12EC
      OR      M260
      ANI     X7  ; PB.Reset
      ANI     M280
      OUT     M260
1242  LD      M143  ; A.Send Data to Trace End
      OR      M1302
      AND     X12E6  ; TraceLeak Test #1
      AND     X12EA
      SET     M251
1247  LD      X12ED
      OR      M261
      ANI     X7  ; PB.Reset
      ANI     M280
      OUT     M261
1252  LD      M143  ; A.Send Data to Trace End
      OR      M1302
      AND     X12E7  ; TraceLeak Test #2
      AND     X12EB
      ANI     M262
      SET     M252
1258  LD      X12EE
      OR      M262
      ANI     X7  ; PB.Reset
      ANI     M252
      ANI     M280
      OUT     M262
1264  LDF     M143  ; A.Send Data to Trace End
      SET     M280
1266  LD      M280
      OUT     T40 K5
1271  LDP     T40
      RST     M280
1273  LD      M130  ; A.CycleEnd
      OR      M407  ; PB.Reset
      FMOV    K0 K2Y36 K1
      FMOV    K0 K2M250 K1
      RST     M270
      RST     M271
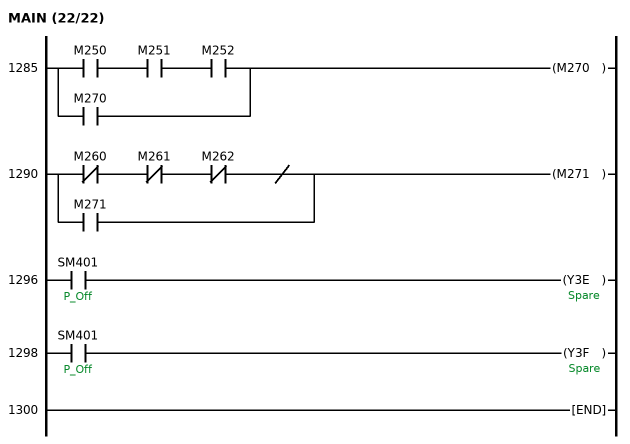
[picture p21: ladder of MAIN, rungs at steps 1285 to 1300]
1285  LD      M250
      AND     M251
      AND     M252
      OR      M270
      OUT     M270
1290  LDI     M260
      ANI     M261
      ANI     M262
      INV
      OR      M271
      OUT     M271
1296  LD      SM401  ; P_Off
      OUT     Y3E  ; Spare
1298  LD      SM401  ; P_Off
      OUT     Y3F  ; Spare
1300  END
END_PROGRAM

// device comments not shown above
X101  ; QR
M10  ; Home by NG
M11  ; HomeByNGRun
M12  ; HomeEnd
M20  ; Ch.Pro.Bit1
M21  ; Ch.Pro.Bit2
M22  ; Ch.Pro.Bit4
M23  ; Ch.Pro.Bit8
M70  ; Hyd.PumpOn
M206  ; M.ALT Test
M207  ; M.ALT Test End
M1003  ; 3_Air Leak Test Controller Alarm
M1008  ; 8_
M1009  ; 9_
M1010  ; 10_
M1011  ; 11_
M1012  ; 12_
M1013  ; 13_
M1014  ; 14_
M1015  ; 15_
M1038  ; 38_
M1039  ; 39_
M1040  ; 40_
M1041  ; 41_
M1042  ; 42_
M1043  ; 43_
M1044  ; 44
M1045  ; 45
M1046  ; 46
M1047  ; 47
M1048  ; 48
M1049  ; 49
M1050  ; 50
M1051  ; 51
M1052  ; 52
M1053  ; 53
M1054  ; 54
M1055  ; 55
M1056  ; 56
M1057  ; 57
M1058  ; 58
M1059  ; 59
M1060  ; 60
M1061  ; 61
M1062  ; 62
M1063  ; 63
M1065  ; 65
M1066  ; 66
M1067  ; 67
M1068  ; 68
M1069  ; 69
M1070  ; 70
M1071  ; 71
M1072  ; 72
M1073  ; 73
M1074  ; 74
M1075  ; 75
M1076  ; 76
M1077  ; 77
M1078  ; 78
M1079  ; 79
M1110  ; Complete
B1  ; ALT.NG UL
B2  ; ALT.NG LL
B3  ; ALT.Error
D606  ; Dayof Week
W8F  ; 2D Code [8]
W90  ; 2D Read Date [Year]
W91  ; 2D Read Date [Mount]
W9E  ; Laser2DCode[9]
W9F  ; Laser2DCode[10]
